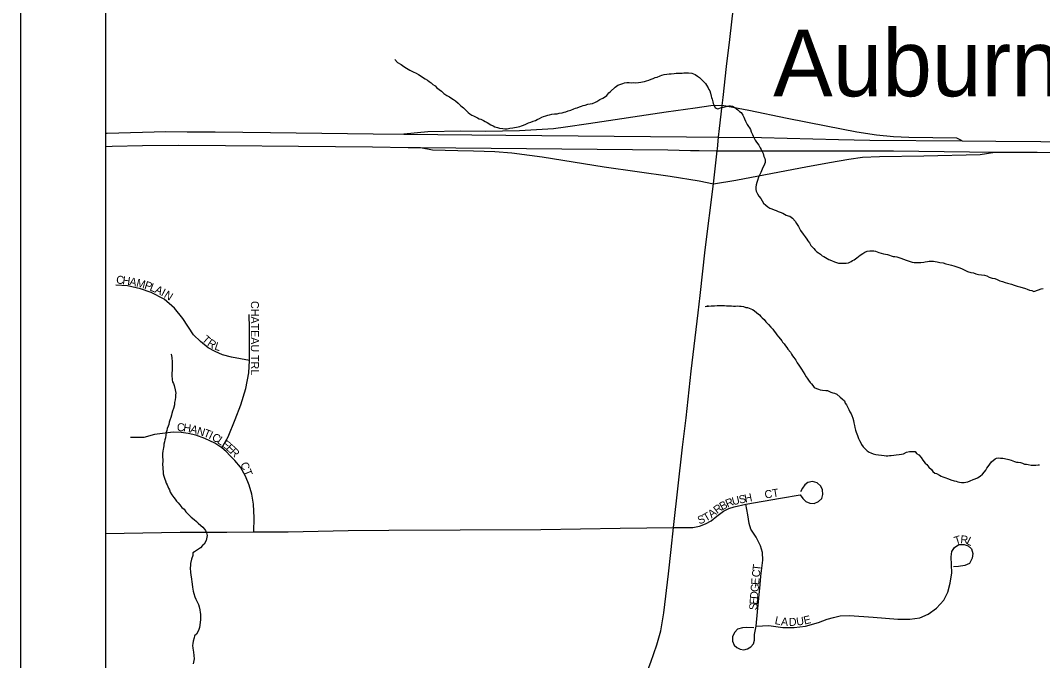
# Model space of a CAD drawing. Extents: x 10.6 to 44.6, y -2.6 to 23.4.
# Drawn here: x 13.103 to 14.313, y 17.35 to 18.108 of the extents above; entities that cross this region are included whole.
import ezdxf

# ---------------------------------------------------------------- set-up
doc = ezdxf.new("R2010")
doc.units = 0
for name, color, linetype in [('GM_X_County', 7, 'Continuous'), ('GM_X_Interchange_Ramps', 7, 'Continuous'), ('GM_X_Minor_River', 7, 'Continuous'), ('GM_X_State_Route', 7, 'Continuous'), ('GM_X_Township', 7, 'Continuous'), ('GM_X_Township_Road', 7, 'Continuous'), ('GM_X_Township_Subdivision', 7, 'Continuous'), ('GM_X_Township_Subdivision_Text', 7, 'Continuous'), ('GM_X_Unincorporated_Text', 7, 'Continuous'), ('GM_X_US_Route', 7, 'Continuous'), ('SH_Data', 7, 'Continuous')]:
    doc.layers.add(name, color=color, linetype=linetype)

msp = doc.modelspace()

# ---------------------------------------------------------------- linework, layer by layer
at = {"layer": 'GM_X_County'}
msp.add_lwpolyline([(20.0033, 15.5302), (20.0033, 22.3267), (13.2033, 22.3267), (13.2033, 15.5267), (19.8413, 15.5267)], dxfattribs=at)
at = {"layer": 'GM_X_Interchange_Ramps'}
for points in [[(13.9333, 18.0068), (13.9201, 18.0065), (13.9015, 18.0038), (13.867, 17.9989), (13.7751, 17.985), (13.7479, 17.9811), (13.7337, 17.9792), (13.6934, 17.9768), (13.6531, 17.9761), (13.6241, 17.9764), (13.5851, 17.9756), (13.5566, 17.9728)], [(14.2176, 17.9649), (14.2112, 17.9684), (14.1545, 17.9691), (14.1361, 17.9696), (14.116, 17.9716), (14.0927, 17.9755), (14.0564, 17.9824), (14.0102, 17.9917), (13.9649, 18.0009), (13.9333, 18.0068)], [(13.5763, 17.9572), (13.5905, 17.9543), (13.6205, 17.9535), (13.6389, 17.9534), (13.6644, 17.9525), (13.6846, 17.9507), (13.7053, 17.9482), (13.7204, 17.9462), (13.7939, 17.9342), (13.8717, 17.9232), (13.9062, 17.9178), (13.9231, 17.9142)], [(13.9231, 17.9142), (13.9496, 17.9183), (14.0012, 17.9282), (14.0323, 17.9342), (14.0604, 17.9394), (14.0832, 17.9435), (14.0996, 17.9457), (14.1196, 17.9466), (14.1721, 17.9473), (14.2389, 17.949), (14.256, 17.9515)]]:
    msp.add_lwpolyline(points, dxfattribs=at)
at = {"layer": 'GM_X_Minor_River'}
for points in [[(13.546, 18.0613), (13.5491, 18.0579), (13.5534, 18.0554), (13.5565, 18.0532), (13.5599, 18.0513), (13.5638, 18.0488), (13.5676, 18.0469), (13.5711, 18.0451), (13.5738, 18.0436), (13.5819, 18.0385), (13.5846, 18.037), (13.5865, 18.0352), (13.5888, 18.0337), (13.5911, 18.0319), (13.5935, 18.03), (13.5958, 18.0278), (13.5985, 18.0259), (13.6012, 18.0237), (13.6039, 18.0211), (13.6074, 18.0189), (13.6105, 18.0171), (13.6136, 18.0152), (13.6155, 18.0141), (13.6178, 18.0123), (13.6209, 18.0097), (13.624, 18.0067), (13.6271, 18.0041), (13.6298, 18.0015), (13.6329, 17.9986), (13.6349, 17.9971), (13.6372, 17.9956), (13.6391, 17.9945), (13.6414, 17.9934), (13.6437, 17.9923), (13.6456, 17.9912), (13.6479, 17.9909), (13.651, 17.9891), (13.6529, 17.988), (13.6552, 17.9869), (13.6595, 17.9839), (13.6622, 17.9829), (13.6645, 17.9818), (13.6675, 17.9807), (13.6698, 17.98), (13.6737, 17.9797), (13.6763, 17.9794), (13.679, 17.9794), (13.682, 17.9799), (13.6858, 17.9803), (13.6919, 17.9816), (13.6938, 17.982), (13.6957, 17.9828), (13.6983, 17.9836), (13.7009, 17.9848), (13.7043, 17.9864), (13.707, 17.9873), (13.7096, 17.9885), (13.7123, 17.9893), (13.7145, 17.9905), (13.7171, 17.9917), (13.7198, 17.9929), (13.7221, 17.9937), (13.7247, 17.9945), (13.727, 17.9953), (13.7292, 17.9957), (13.7319, 17.9965), (13.7349, 17.997), (13.738, 17.997), (13.7406, 17.9979), (13.744, 17.9983), (13.7463, 17.9991), (13.7482, 17.9996), (13.7512, 18.0004), (13.7542, 18.0012), (13.758, 18.0028), (13.7599, 18.0036), (13.7618, 18.004), (13.7644, 18.0052), (13.7667, 18.006), (13.7689, 18.0068), (13.7712, 18.0073), (13.7742, 18.0085), (13.7773, 18.0089), (13.7799, 18.0094), (13.7833, 18.011), (13.7852, 18.0118), (13.7886, 18.0141), (13.7923, 18.0157), (13.7942, 18.0169), (13.7968, 18.0189), (13.7994, 18.0219), (13.8013, 18.0235), (13.8069, 18.0286), (13.8099, 18.0309), (13.8133, 18.0321), (13.8159, 18.0329), (13.8178, 18.0337), (13.8205, 18.0342), (13.8235, 18.0343), (13.8258, 18.0339), (13.8285, 18.034)], [(13.8285, 18.034), (13.8308, 18.0336), (13.8342, 18.0341), (13.8372, 18.0345), (13.8391, 18.035), (13.8414, 18.0354), (13.844, 18.0362), (13.8467, 18.037), (13.8493, 18.0379), (13.8519, 18.039), (13.8542, 18.0399), (13.8565, 18.0403), (13.8599, 18.0419), (13.8618, 18.0427), (13.8648, 18.0435), (13.8678, 18.044), (13.8708, 18.0444), (13.8731, 18.0444), (13.8765, 18.0449), (13.8788, 18.045), (13.8819, 18.045), (13.8838, 18.0451), (13.886, 18.0451), (13.8879, 18.0455), (13.8898, 18.0456), (13.8917, 18.0456), (13.8936, 18.0457), (13.8975, 18.045), (13.9013, 18.0435), (13.904, 18.0417), (13.9067, 18.0402), (13.9086, 18.038), (13.9118, 18.035), (13.9137, 18.0328), (13.9149, 18.0309), (13.9168, 18.0279), (13.9176, 18.026), (13.9188, 18.0242), (13.9196, 18.0215), (13.9205, 18.0181), (13.9209, 18.0162), (13.9217, 18.0143), (13.9225, 18.0113), (13.9226, 18.0094), (13.9238, 18.0068), (13.925, 18.0041), (13.9284, 18.0031), (13.9326, 18.0047), (13.9348, 18.0051), (13.9413, 18.0064), (13.9432, 18.0064), (13.9458, 18.0061), (13.9482, 18.0047), (13.952, 18.0017), (13.954, 17.9998), (13.9559, 17.9987), (13.9579, 17.9954), (13.9591, 17.9931), (13.9599, 17.9912), (13.9611, 17.9882), (13.963, 17.9845), (13.9646, 17.9822), (13.9658, 17.9803), (13.967, 17.9785), (13.9678, 17.9758), (13.9694, 17.9724), (13.9702, 17.9705), (13.9714, 17.9683), (13.9726, 17.9657), (13.9741, 17.9634), (13.9769, 17.9601), (13.9785, 17.9567), (13.9796, 17.9548), (13.9812, 17.9518), (13.982, 17.9499), (13.9829, 17.9465), (13.9837, 17.9442), (13.9841, 17.9423), (13.9842, 17.9393), (13.9834, 17.9374), (13.9809, 17.9316), (13.9798, 17.9297), (13.9791, 17.9274), (13.978, 17.9251), (13.9765, 17.922), (13.9751, 17.9182), (13.9744, 17.9159), (13.9737, 17.9129), (13.9734, 17.9102), (13.9734, 17.9075), (13.9735, 17.9053), (13.9751, 17.9022), (13.9766, 17.8996), (13.979, 17.8966), (13.9806, 17.894), (13.9825, 17.8914), (13.9849, 17.8888), (13.9876, 17.8869), (13.9899, 17.8855), (13.9922, 17.8844), (13.9949, 17.8833)], [(13.9949, 17.8833), (13.9972, 17.8826), (13.9995, 17.8815), (14.0022, 17.8804), (14.0052, 17.8793), (14.0071, 17.8782), (14.0091, 17.8771), (14.0114, 17.8764), (14.0133, 17.8757), (14.0168, 17.8735), (14.0199, 17.8698), (14.0215, 17.8672), (14.0238, 17.8638), (14.0262, 17.8589), (14.0293, 17.8544), (14.0317, 17.8514), (14.0336, 17.8488), (14.0348, 17.8465), (14.0368, 17.8443), (14.0384, 17.8413), (14.0419, 17.8376), (14.0434, 17.8357), (14.0454, 17.8338), (14.0473, 17.8324), (14.0496, 17.8309), (14.0516, 17.829), (14.0539, 17.828), (14.0558, 17.8269), (14.0577, 17.8258), (14.0596, 17.8247), (14.0627, 17.8232), (14.0662, 17.8218), (14.0711, 17.8203), (14.0769, 17.8201), (14.0803, 17.8202), (14.0829, 17.8206), (14.0859, 17.8222), (14.0878, 17.8234), (14.0897, 17.8242), (14.0927, 17.8265), (14.0946, 17.8281), (14.0968, 17.8296), (14.0998, 17.8316), (14.1024, 17.8332), (14.1051, 17.8344), (14.1081, 17.8348), (14.1112, 17.8349), (14.1131, 17.8346), (14.115, 17.8342), (14.1169, 17.8335), (14.1188, 17.8328), (14.1215, 17.8321), (14.1242, 17.8314), (14.1268, 17.8307), (14.1291, 17.8303), (14.1314, 17.8296), (14.1333, 17.8289), (14.1356, 17.8282), (14.1379, 17.8279), (14.1402, 17.8275), (14.1425, 17.8268), (14.1448, 17.8261), (14.1513, 17.8236), (14.1536, 17.8229), (14.1559, 17.8222), (14.1582, 17.8215), (14.1605, 17.8208), (14.1632, 17.8208), (14.1659, 17.8209), (14.1685, 17.8209), (14.1719, 17.8214), (14.1738, 17.8218), (14.1765, 17.8223), (14.1784, 17.8227), (14.1818, 17.8224), (14.1837, 17.8224), (14.1856, 17.8221), (14.1879, 17.8217), (14.191, 17.821), (14.1948, 17.8204), (14.1982, 17.8193), (14.2017, 17.8186), (14.2047, 17.8179), (14.2078, 17.8169), (14.2112, 17.8158), (14.2147, 17.8147), (14.2174, 17.8133), (14.2208, 17.8118), (14.2239, 17.8104), (14.2277, 17.8093), (14.2308, 17.8086), (14.2338, 17.8075), (14.2369, 17.8068), (14.2403, 17.8062), (14.2438, 17.8059), (14.2465, 17.8052), (14.2495, 17.8037), (14.253, 17.8026), (14.256, 17.8019), (14.2587, 17.8009), (14.2622, 17.7994)], [(14.2622, 17.7994), (14.2652, 17.7983), (14.2683, 17.7973), (14.271, 17.7966), (14.2729, 17.7962), (14.276, 17.7952), (14.279, 17.7941), (14.2825, 17.793), (14.2859, 17.7923), (14.2924, 17.7902), (14.2943, 17.7895), (14.297, 17.7884), (14.3001, 17.7877), (14.3024, 17.7866), (14.308, 17.7886), (14.3111, 17.7898), (14.3133, 17.7903)], [(13.9132, 17.7687), (13.9174, 17.7691), (13.9151, 17.7691), (13.9174, 17.7691), (13.9204, 17.7696), (13.9223, 17.7696), (13.9243, 17.7697), (13.9273, 17.7701), (13.9296, 17.7701), (13.9318, 17.7702), (13.9341, 17.7702), (13.936, 17.7699), (13.9387, 17.7696), (13.9421, 17.7697), (13.9444, 17.7697), (13.9467, 17.7694), (13.949, 17.7694), (13.9516, 17.7695), (13.9539, 17.7692), (13.9558, 17.7692), (13.9585, 17.7689), (13.9616, 17.7678), (13.9635, 17.7675), (13.9692, 17.7653), (13.9712, 17.7642), (13.9746, 17.7612), (13.9777, 17.759), (13.9793, 17.7572), (13.9809, 17.7553), (13.9832, 17.7534), (13.9851, 17.7508), (13.9882, 17.7475), (13.991, 17.7445), (13.9933, 17.7419), (13.9949, 17.7396), (13.9964, 17.7378), (13.998, 17.7355), (14, 17.7329), (14.0023, 17.7303), (14.0039, 17.7284), (14.005, 17.7266), (14.0066, 17.7247), (14.0082, 17.7221), (14.0101, 17.7202), (14.0113, 17.7183), (14.0141, 17.7146), (14.0156, 17.7124), (14.0168, 17.7105), (14.0184, 17.7086), (14.0207, 17.7052), (14.0223, 17.7022), (14.0243, 17.6992), (14.0274, 17.6947), (14.0294, 17.6914), (14.0314, 17.6884), (14.0329, 17.6857), (14.0341, 17.6839), (14.0357, 17.6816), (14.0376, 17.679), (14.0392, 17.6771), (14.0408, 17.6753), (14.0423, 17.673), (14.045, 17.6716), (14.0473, 17.6709), (14.0492, 17.6701), (14.0523, 17.6698), (14.0561, 17.6695), (14.058, 17.6692), (14.0619, 17.6674), (14.0645, 17.6667), (14.0664, 17.6663), (14.0691, 17.6649), (14.073, 17.6615), (14.0753, 17.6597), (14.078, 17.6571), (14.0789, 17.6544), (14.0804, 17.6526), (14.0816, 17.6499), (14.0832, 17.6469), (14.0844, 17.6443), (14.086, 17.6417), (14.0868, 17.6398), (14.088, 17.6368), (14.0888, 17.6338), (14.0892, 17.6311), (14.0901, 17.6281), (14.0905, 17.6254), (14.0913, 17.6224), (14.0921, 17.6201), (14.0934, 17.616), (14.0946, 17.6126), (14.0958, 17.6103), (14.0974, 17.6073), (14.0985, 17.6055), (14.1001, 17.6028), (14.1025, 17.6002), (14.1052, 17.598), (14.1075, 17.5965), (14.1094, 17.5954), (14.1121, 17.5944), (14.1152, 17.5937)], [(13.2815, 17.712), (13.2814, 17.7124), (13.2819, 17.7086), (13.2824, 17.7029), (13.2825, 17.6991), (13.2825, 17.6964), (13.2822, 17.693), (13.2819, 17.6903), (13.282, 17.6877), (13.2825, 17.682), (13.2829, 17.6797), (13.2841, 17.6775), (13.2849, 17.6752), (13.2861, 17.6703), (13.2866, 17.6661), (13.2863, 17.6642), (13.2863, 17.6616), (13.286, 17.6585), (13.2853, 17.6551), (13.285, 17.6524), (13.284, 17.6482), (13.2829, 17.6451), (13.2818, 17.6421), (13.2815, 17.6402), (13.2808, 17.6375), (13.2797, 17.6344), (13.279, 17.6318), (13.2783, 17.6291), (13.2776, 17.6272), (13.2765, 17.6245), (13.2761, 17.6222), (13.2754, 17.6195), (13.2747, 17.6165), (13.2744, 17.6134), (13.2737, 17.6111), (13.2734, 17.6084), (13.2727, 17.6058), (13.2724, 17.6039), (13.272, 17.602), (13.2717, 17.5997), (13.2713, 17.5978), (13.271, 17.5943), (13.2711, 17.5924), (13.2711, 17.5905), (13.2712, 17.5875), (13.2712, 17.5848), (13.2709, 17.5829), (13.2709, 17.581), (13.2714, 17.5791), (13.2719, 17.5708), (13.2724, 17.5678), (13.2736, 17.5644), (13.2744, 17.5625), (13.2752, 17.5598), (13.2764, 17.5576), (13.2772, 17.5557), (13.278, 17.5538), (13.2792, 17.5516), (13.28, 17.5489), (13.282, 17.5459), (13.2843, 17.5426), (13.2859, 17.5407), (13.2874, 17.5384), (13.2894, 17.5362), (13.2913, 17.534), (13.2937, 17.531), (13.2964, 17.5288), (13.2987, 17.5258), (13.3019, 17.5224), (13.305, 17.5194), (13.3084, 17.5165), (13.3112, 17.5143), (13.3131, 17.5124), (13.3162, 17.5094), (13.3185, 17.5076), (13.3205, 17.5053), (13.3217, 17.5035), (13.3229, 17.5008), (13.3237, 17.4978), (13.3227, 17.4917), (13.3201, 17.4875), (13.3182, 17.4859), (13.316, 17.4832), (13.3134, 17.4816), (13.3111, 17.4801), (13.3089, 17.4785), (13.307, 17.4773), (13.3067, 17.4739), (13.3053, 17.4697), (13.3042, 17.4647), (13.3039, 17.4624), (13.3036, 17.459), (13.3041, 17.4544), (13.3045, 17.4507), (13.3049, 17.4488), (13.3054, 17.4461), (13.3058, 17.4427), (13.3059, 17.44), (13.3063, 17.4366), (13.3072, 17.4317), (13.308, 17.4291)], [(14.1152, 17.5937), (14.1251, 17.5924), (14.1274, 17.592), (14.1293, 17.5921), (14.1315, 17.5925), (14.1334, 17.5925), (14.1365, 17.593), (14.1395, 17.5931), (14.1429, 17.5935), (14.1456, 17.5939), (14.1479, 17.5944), (14.1516, 17.5964), (14.155, 17.5972), (14.1569, 17.5972), (14.16, 17.5973), (14.1619, 17.597), (14.1634, 17.5947), (14.1661, 17.5933), (14.1689, 17.5899), (14.1708, 17.5869), (14.1736, 17.5835), (14.1755, 17.5817), (14.1782, 17.5787), (14.181, 17.5757), (14.1829, 17.5735), (14.1852, 17.5716), (14.1872, 17.5709), (14.1906, 17.5691), (14.1925, 17.568), (14.1945, 17.5673), (14.1968, 17.5662), (14.2014, 17.5648), (14.204, 17.5637), (14.2079, 17.5626), (14.2105, 17.5619), (14.2125, 17.5612), (14.2144, 17.5609), (14.2167, 17.5605), (14.2197, 17.5606), (14.222, 17.561), (14.2243, 17.5614), (14.2269, 17.5623), (14.2303, 17.5639), (14.2329, 17.5647), (14.2356, 17.5659), (14.2386, 17.5678), (14.2416, 17.5702), (14.2438, 17.5729), (14.2453, 17.5752), (14.2467, 17.5775), (14.2482, 17.5795), (14.2504, 17.5822), (14.2523, 17.5849), (14.2564, 17.5884), (14.2583, 17.5892), (14.2609, 17.5896), (14.2628, 17.5893), (14.2655, 17.5893), (14.2674, 17.589), (14.2728, 17.5876), (14.2754, 17.5869), (14.2793, 17.5854), (14.2816, 17.5847), (14.2839, 17.5844), (14.2865, 17.5841), (14.2888, 17.5834), (14.2911, 17.5823), (14.2938, 17.582), (14.2957, 17.5816), (14.2992, 17.5809), (14.3011, 17.581), (14.3045, 17.5811), (14.3075, 17.5815), (14.309, 17.5815)], [(13.308, 17.4291), (13.3093, 17.4249), (13.3105, 17.4223), (13.312, 17.4193), (13.3136, 17.4159), (13.3144, 17.4132), (13.3153, 17.4098), (13.3157, 17.4064), (13.3158, 17.4045), (13.3158, 17.4023), (13.3159, 17.3981), (13.3153, 17.3916), (13.3146, 17.3889), (13.3135, 17.3851), (13.311, 17.3809), (13.3087, 17.3789), (13.3084, 17.3766), (13.3073, 17.3724), (13.307, 17.3698), (13.3063, 17.3675), (13.3067, 17.3641), (13.3076, 17.3595), (13.3085, 17.3515), (13.3071, 17.3458)]]:
    msp.add_lwpolyline(points, dxfattribs=at)
at = {"layer": 'GM_X_State_Route'}
for points in [[(13.9344, 18.0165), (13.9384, 18.053), (13.9423, 18.0849), (13.9487, 18.1412), (13.9488, 18.142)], [(13.9278, 17.9554), (13.9291, 17.9693), (13.9301, 17.9795), (13.9333, 18.0068), (13.9344, 18.0165)], [(13.9231, 17.9142), (13.9231, 17.9142), (13.9276, 17.9534), (13.9278, 17.9554)], [(13.9072, 17.782), (13.9134, 17.8361), (13.9231, 17.9142)], [(13.7599, 17.123), (13.7686, 17.1451), (13.7903, 17.1995), (13.8195, 17.2727), (13.8354, 17.3127), (13.8491, 17.3477), (13.8562, 17.3681), (13.8607, 17.3848), (13.8642, 17.4061), (13.8698, 17.4521), (13.873, 17.4809), (13.8758, 17.5073), (13.8865, 17.6023), (13.8906, 17.637), (13.8967, 17.6921), (13.9048, 17.7613), (13.9072, 17.782)]]:
    msp.add_lwpolyline(points, dxfattribs=at)
at = {"layer": 'GM_X_Township'}
msp.add_lwpolyline([(13.2033, 20.8217), (13.2033, 15.5267), (15.2903, 15.5267)], dxfattribs=at)
at = {"layer": 'GM_X_Township_Road'}
msp.add_lwpolyline([(13.2033, 17.5), (13.292, 17.5017), (13.3221, 17.5017), (13.3471, 17.5017), (13.3789, 17.5022), (13.4196, 17.5022), (13.4908, 17.5035), (13.5389, 17.504), (13.6234, 17.5044), (13.7186, 17.5049), (13.8125, 17.5062), (13.8758, 17.5073)], dxfattribs=at)
at = {"layer": 'GM_X_Township_Subdivision'}
for points in [[(13.3739, 17.7048), (13.3527, 17.7089), (13.3419, 17.7118), (13.3332, 17.7156), (13.325, 17.7199), (13.3158, 17.7273), (13.3077, 17.7354), (13.2951, 17.7546), (13.2852, 17.7667), (13.2728, 17.7775), (13.2577, 17.7856), (13.2451, 17.7899), (13.2296, 17.7933), (13.2156, 17.7942)], [(13.341, 17.6015), (13.3485, 17.6145), (13.357, 17.6352), (13.3636, 17.6526), (13.3696, 17.6717), (13.3732, 17.6902), (13.3739, 17.7048), (13.3739, 17.7431), (13.3735, 17.7593)], [(13.3789, 17.5022), (13.3793, 17.5184), (13.3786, 17.5348), (13.3768, 17.5465), (13.3735, 17.5571), (13.369, 17.5681), (13.3633, 17.5785), (13.3566, 17.5864), (13.3509, 17.5922), (13.3464, 17.5972), (13.341, 17.6015), (13.3327, 17.6069), (13.321, 17.6125), (13.3104, 17.6163), (13.3012, 17.6186), (13.2929, 17.6195), (13.2834, 17.6199), (13.2742, 17.619), (13.2616, 17.6172), (13.2487, 17.6136), (13.233, 17.6138)], [(13.8758, 17.5073), (13.8906, 17.5071), (13.8985, 17.5073), (13.9067, 17.5086), (13.9138, 17.5114), (13.9202, 17.5152), (13.9271, 17.5204), (13.9348, 17.5264), (13.9411, 17.5298), (13.9475, 17.5318), (13.9615, 17.5348), (14.0023, 17.5419), (14.0259, 17.5457), (14.0287, 17.5416), (14.0324, 17.5378), (14.0371, 17.5358), (14.0422, 17.5354), (14.0474, 17.5378), (14.0513, 17.5416), (14.0525, 17.5464), (14.0521, 17.5517), (14.05, 17.556), (14.0457, 17.5599), (14.0403, 17.5616), (14.0349, 17.5603), (14.0313, 17.5575), (14.0283, 17.5537), (14.0263, 17.5494)], [(13.9709, 17.3883), (13.9623, 17.3887), (13.9574, 17.3883), (13.9514, 17.3866), (13.9484, 17.3833), (13.9456, 17.378), (13.9458, 17.3726), (13.9477, 17.3679), (13.9507, 17.3651), (13.9548, 17.3629), (13.9589, 17.3623), (13.9632, 17.3636), (13.9675, 17.3657), (13.9705, 17.3694), (13.9716, 17.3739), (13.9716, 17.3803), (13.9735, 17.3904), (13.9752, 17.4072), (13.9782, 17.4398), (13.9793, 17.4497), (13.9815, 17.4686), (13.981, 17.4776), (13.9787, 17.4854), (13.9735, 17.4957), (13.9675, 17.5053), (13.9653, 17.512), (13.9636, 17.5223), (13.9615, 17.5348)], [(13.9735, 17.3904), (13.9888, 17.3909), (14.0053, 17.3887), (14.0186, 17.3889), (14.0319, 17.3902), (14.0476, 17.3947), (14.0577, 17.3984), (14.065, 17.4005), (14.0732, 17.4027), (14.0843, 17.4031), (14.112, 17.401), (14.1413, 17.3986), (14.1554, 17.3986), (14.1675, 17.4003), (14.1773, 17.4046), (14.1872, 17.4117), (14.1958, 17.4211), (14.2005, 17.4306), (14.2033, 17.4413), (14.2053, 17.4536), (14.2044, 17.4723), (14.2053, 17.4789), (14.2085, 17.4836), (14.2136, 17.4869), (14.2197, 17.4871), (14.2244, 17.4856), (14.2285, 17.4817), (14.2302, 17.4763), (14.2295, 17.4708), (14.2263, 17.4645), (14.2207, 17.462), (14.213, 17.4611), (14.2072, 17.4605)]]:
    msp.add_lwpolyline(points, dxfattribs=at)
at = {"layer": 'GM_X_US_Route'}
for points in [[(13.2033, 17.9742), (13.2053, 17.9743), (13.2747, 17.976), (13.3002, 17.9758), (13.3334, 17.9756), (13.3986, 17.9749), (13.5204, 17.9732), (13.5566, 17.9728), (13.6775, 17.9717), (13.8912, 17.9696), (13.9291, 17.9693), (13.9799, 17.9689), (14.071, 17.9666), (14.1081, 17.9659), (14.2176, 17.9649), (14.2573, 17.9646), (14.3107, 17.9642), (14.4676, 17.9618)], [(13.2033, 17.9584), (13.2113, 17.9588), (13.2471, 17.9597), (13.2899, 17.9601), (13.3455, 17.9597), (13.4318, 17.9586), (13.5197, 17.9578), (13.5617, 17.9573), (13.5763, 17.9572), (13.8689, 17.9543), (13.8961, 17.9537), (13.9062, 17.9536)], [(13.9062, 17.9536), (13.9261, 17.9534)], [(13.9261, 17.9534), (13.9276, 17.9534), (14.121, 17.9533), (14.1361, 17.9531)], [(14.1361, 17.9531), (14.256, 17.9515), (14.3064, 17.9515), (14.4013, 17.9505), (14.492, 17.9496), (14.6155, 17.9479), (14.625, 17.9478)]]:
    msp.add_lwpolyline(points, dxfattribs=at)
at = {"layer": 'SH_Data'}
msp.add_line((13.1028, 22.4265), (13.1028, 15.4265), dxfattribs=at)

# ---------------------------------------------------------------- texts
at = {"layer": 'GM_X_Township_Subdivision_Text'}
for s, rotation, p in [('C', 353.1852, (13.2157, 17.7963)), ('H', 351.9533, (13.2231, 17.7954)), ('A', 348.5143, (13.2312, 17.7943)), ('M', 345.7385, (13.2393, 17.7927)), ('P', 341.5737, (13.2488, 17.7903)), ('L', 337.9602, (13.255, 17.7882)), ('A', 334.08, (13.261, 17.7858)), ('I', 332.3208, (13.2684, 17.7822)), ('N', 327.7166, (13.2719, 17.7803)), ('CHATEAU TRL', 270, (13.3756, 17.7754)), ('T', 317.5315, (13.3168, 17.7288)), ('R', 327.3703, (13.3231, 17.7232)), ('L', 341.8924, (13.3318, 17.7181)), ('C', 357.9355, (13.2879, 17.6213)), ('H', 351.6195, (13.2951, 17.6211)), ('A', 344.3788, (13.3031, 17.6199)), ('N', 342.8298, (13.311, 17.6177)), ('T', 338.782, (13.3188, 17.6153)), ('I', 334.9408, (13.3249, 17.613)), ('C', 331.0775, (13.3285, 17.6113)), ('L', 325.787, (13.3349, 17.6078)), ('E', 322.1466, (13.3403, 17.6041)), ('E', 317.0682, (13.3454, 17.6002)), ('R', 315.2405, (13.3502, 17.5957)), ('CT', 292.4212, (13.3628, 17.5824)), ('U', 13.5485, (13.9461, 17.5334)), ('S', 11.7226, (13.9541, 17.5353)), ('H', 11.6399, (13.9607, 17.5367)), ('CT', 9.4702, (13.9844, 17.5413)), ('R', 36.4327, (13.9274, 17.5229)), ('B', 27.9339, (13.9332, 17.5272)), ('R', 22.7712, (13.9396, 17.5306)), ('S', 21.4259, (13.9064, 17.5107)), ('T', 30.6187, (13.9141, 17.5138)), ('A', 37.2186, (13.9208, 17.5179)), ('T', 17.6572, (14.2097, 17.4866)), ('R', 355.5026, (14.2151, 17.4885)), ('L', 333.3372, (14.2217, 17.4882)), ('T', 83.3189, (13.9786, 17.4553)), ('E', 85.3418, (13.977, 17.4388)), ('C', 83.9897, (13.9778, 17.4478)), ('G', 85.2962, (13.9763, 17.4305)), ('E', 85.3027, (13.9751, 17.4155)), ('D', 85.318, (13.9756, 17.4222)), ('S', 85.3226, (13.9746, 17.4089)), ('L', 348.3365, (13.9951, 17.393)), ('A', 353.9888, (14.0027, 17.3914)), ('D', 2.3372, (14.0125, 17.3905)), ('U', 7.6896, (14.0217, 17.3909)), ('E', 12.9969, (14.0309, 17.3922))]:
    msp.add_text(s, height=0.00947, rotation=rotation, dxfattribs=at).set_placement(p)
at = {"layer": 'GM_X_Unincorporated_Text'}
msp.add_text('Auburn Corners', height=0.078977, rotation=0, dxfattribs=at).set_placement((13.9938, 18.0178))

doc.saveas('drawing.dxf')
